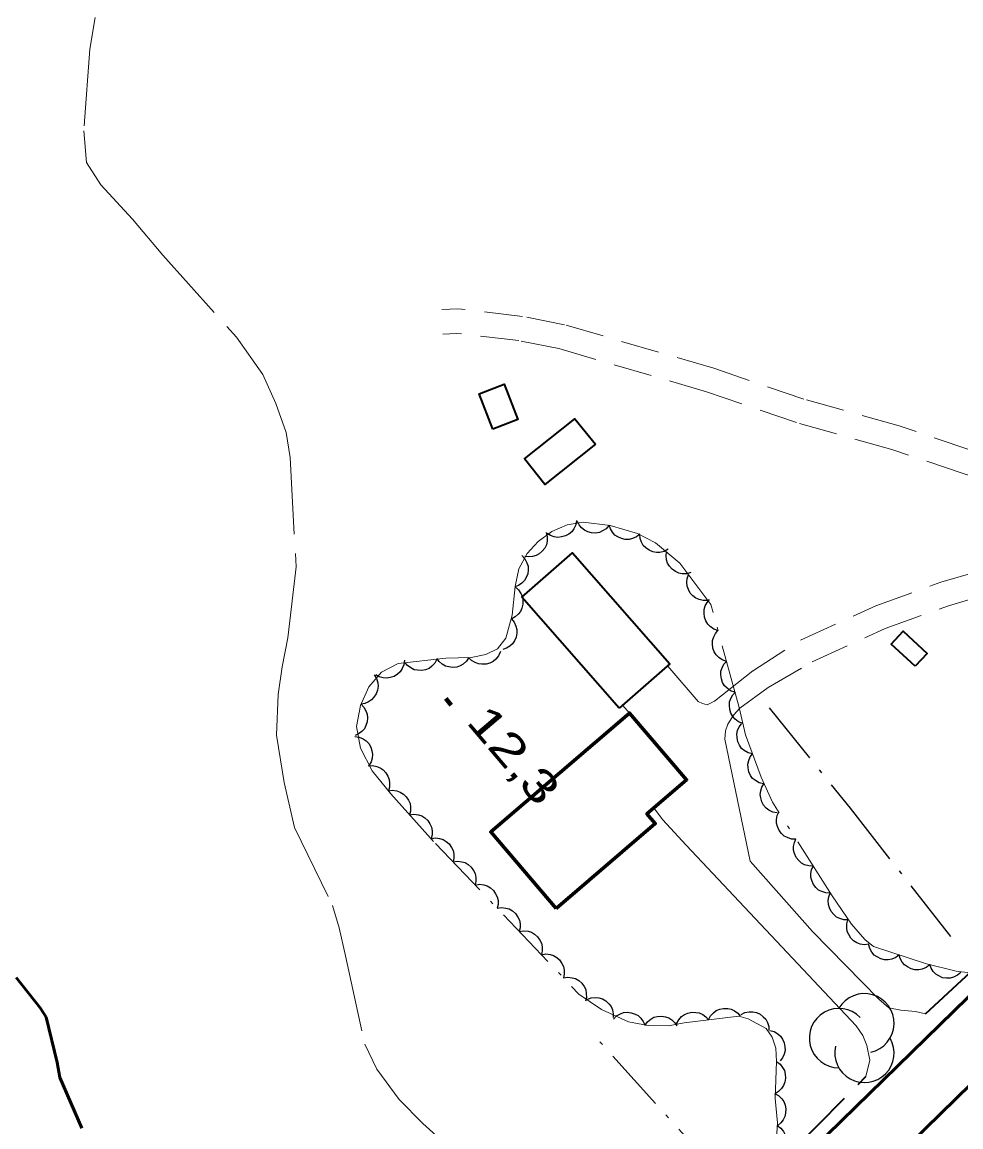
# Model space of a CAD drawing. Extents: x 386081 to 389416, y 5130568 to 5134082.
# Drawn here: x 387086.1 to 387174, y 5132079.6 to 5132183 of the extents above; entities that cross this region are included whole.
import ezdxf

# ---------------------------------------------------------------- set-up
doc = ezdxf.new("R2010")
doc.units = 0
doc.header["$LTSCALE"] = 1.2
for name, pattern in [('DOT_DASHED', [7.7, 5, -1.2, 0.3, -1.2]), ('LONG_DASHED', [7.5, 6, -1.5]), ('MEDIUM_DASHED', [4.5, 3, -1.5])]:
    doc.linetypes.add(name, pattern=pattern)
for name, color, linetype, lineweight in [('1', 7, 'Continuous', 53), ('19', 7, 'Continuous', 13), ('2', 7, 'Continuous', 13), ('21', 7, 'LONG_DASHED', 35), ('3', 7, 'Continuous', 140), ('31', 7, 'Continuous', 70), ('41', 7, 'DOT_DASHED', 25), ('44', 7, 'Continuous', 25)]:
    doc.layers.add(name, color=color, linetype=linetype, lineweight=lineweight)

msp = doc.modelspace()

# ---------------------------------------------------------------- linework, layer by layer
at = {"layer": '1', "linetype": 'LONG_DASHED'}
msp.add_lwpolyline([(387085.5, 5132093.55), (387087.75, 5132090.69), (387088.32, 5132089.82), (387089.35, 5132085.57), (387089.59, 5132084.18), (387091.67, 5132079.44)], dxfattribs=at)
at = {"layer": '19'}
msp.add_line((387142.96, 5132118.29), (387142.32, 5132119.01), dxfattribs=at)
at = {"layer": '19', "linetype": 'MEDIUM_DASHED'}
for points in [[(387209.48, 5132128.2), (387207.37, 5132128.87), (387203.75, 5132130.69), (387199.52, 5132133.4), (387195.36, 5132135.58), (387191.22, 5132137.3), (387187.74, 5132138.4), (387182.04, 5132140.71), (387174.91, 5132142.9), (387168.21, 5132145.18), (387159.28, 5132147.68), (387150.86, 5132150.57), (387136.88, 5132154.65), (387132.94, 5132155.43), (387126.88, 5132156.15), (387125.38, 5132156.08)], [(387154.47, 5132122.21), (387158.98, 5132125.13), (387166.02, 5132128.33), (387172.12, 5132130.54), (387177.06, 5132131.99), (387188.02, 5132136.04), (387181.26, 5132138.54), (387174.21, 5132140.71), (387167.53, 5132142.98), (387158.59, 5132145.48), (387150.16, 5132148.37), (387136.33, 5132152.42), (387132.58, 5132153.16), (387126.79, 5132153.84), (387125.48, 5132153.78)], [(387155.94, 5132120.7), (387160.07, 5132123.09), (387166.89, 5132126.2), (387172.83, 5132128.34), (387177.78, 5132129.8), (387188.83, 5132133.88), (387189.46, 5132134.19), (387189.9, 5132134.34), (387190.65, 5132134.44), (387191.33, 5132134.37), (387193.9, 5132133.45), (387198.23, 5132131.18), (387204.42, 5132126.51), (387204.98, 5132125.78), (387205.95, 5132124.13)]]:
    msp.add_lwpolyline(points, dxfattribs=at)
at = {"layer": '19'}
for points in [[(387146.53, 5132122.68), (387149.4, 5132119.38), (387149.78, 5132119.18), (387150.24, 5132119.07), (387150.91, 5132119.41), (387154.52, 5132122.25)], [(387170.67, 5132090.15), (387169.74, 5132090.36), (387168.38, 5132090.48), (387167.24, 5132090.71), (387166.31, 5132091.5), (387160.11, 5132097.84), (387154.27, 5132104.43), (387151.87, 5132115.86), (387151.94, 5132116.63), (387152.17, 5132117.25), (387152.69, 5132118.09), (387153.28, 5132118.76), (387155.94, 5132120.7)], [(387165.08, 5132084.26), (387165.45, 5132085.8), (387165.19, 5132087.18), (387164.82, 5132088.11), (387164.18, 5132089.01), (387148.26, 5132105.93), (387146.04, 5132108.33), (387145.24, 5132109.43)]]:
    msp.add_lwpolyline(points, dxfattribs=at)
at = {"layer": '2', "linetype": 'LONG_DASHED'}
msp.add_lwpolyline([(387092.91, 5132183.41), (387092.4, 5132180.45), (387091.86, 5132172.81), (387092.09, 5132169.85), (387093.45, 5132167.75), (387096.4, 5132164.52), (387099.24, 5132161.17), (387106.14, 5132153.47), (387108.6, 5132150), (387109.83, 5132147.28), (387110.81, 5132144.56), (387111.16, 5132142.22), (387111.73, 5132131.98), (387110.95, 5132125.33), (387110.43, 5132122.62), (387110.05, 5132120.04), (387109.9, 5132116.22), (387110.62, 5132111.78), (387111.59, 5132107.58), (387115.15, 5132100.28), (387115.75, 5132098.18), (387116.36, 5132095.58), (387118.17, 5132087.31), (387119.28, 5132084.96), (387121.37, 5132082.11), (387123.59, 5132079.87), (387125.81, 5132077.88)], dxfattribs=at)
at = {"layer": '21', "linetype": 'Continuous', "lineweight": 53}
for points in [[(387012.51, 5131910.8), (387021.08, 5131926.01), (387027.11, 5131935.62), (387032.84, 5131944.26), (387041.79, 5131956.43), (387052.62, 5131969.96), (387063.03, 5131981.26), (387078.48, 5131997.51), (387098.33, 5132017.4), (387121.9, 5132040.2), (387177.29, 5132094.24), (387231.65, 5132148.34), (387255.86, 5132172.16), (387275.84, 5132191.54), (387323.76, 5132237.29), (387346.1, 5132259.65), (387398.36, 5132310.48), (387454.62, 5132364.63)], [(387164.72, 5131800.51), (387132.8, 5131839.87), (387092.63, 5131890.18), (387081.09, 5131904.74), (387066.45, 5131922.63), (387054.56, 5131937.69), (387051.33, 5131941.01), (387048.28, 5131943.8), (387047.55, 5131945.3), (387046.77, 5131948.88), (387046.55, 5131951.09), (387046.66, 5131953.51), (387053.66, 5131962.18), (387060.66, 5131970.37), (387073.31, 5131984.05), (387083.84, 5131994.54), (387097.28, 5132007.63), (387119.07, 5132029.15), (387136.21, 5132045.69), (387190.72, 5132099), (387248.29, 5132155.99)]]:
    msp.add_lwpolyline(points, dxfattribs=at)
at = {"layer": '21'}
for points in [[(387170.67, 5132090.15), (387174.5, 5132093.65), (387198.02, 5132116.17), (387205.95, 5132124.13)], [(387090.92, 5132011.03), (387104.6, 5132024.53), (387129.07, 5132048.91), (387158.04, 5132077.13), (387165.08, 5132084.26)]]:
    msp.add_lwpolyline(points, dxfattribs=at)
at = {"layer": '3'}
msp.add_line((387125.75, 5132119.65), (387126.26, 5132119.04), dxfattribs=at)
at = {"layer": '31', "lineweight": 35}
for points in [[(387130.15, 5132144.87), (387128.87, 5132148.18), (387131.23, 5132149.09), (387132.51, 5132145.78)], [(387139.76, 5132143.46), (387135.04, 5132139.7), (387133.13, 5132142.09), (387137.85, 5132145.84)], [(387141.98, 5132118.75), (387132.87, 5132129.15), (387137.62, 5132133.3), (387146.73, 5132122.91)], [(387169.7, 5132122.67), (387167.45, 5132124.74), (387168.58, 5132125.96), (387170.83, 5132123.88)]]:
    msp.add_lwpolyline(points, close=True, dxfattribs=at)
at = {"layer": '31'}
msp.add_lwpolyline([(387136.09, 5132100), (387129.96, 5132107.17), (387142.96, 5132118.29), (387148.3, 5132112.05), (387144.58, 5132108.86), (387145.36, 5132107.94)], close=True, dxfattribs=at)
at = {"layer": '41'}
msp.add_line((387151.6, 5132074.88), (387139.49, 5132088.28), dxfattribs=at)
msp.add_lwpolyline([(387156.04, 5132118.77), (387163.61, 5132109.38), (387173.87, 5132096.29)], dxfattribs=at)
at = {"layer": '44', "linetype": 'DOT_DASHED', "lineweight": 13}
for points in [[(387170.77, 5132094.82), (387165.81, 5132096.44), (387164.99, 5132097.09), (387163.74, 5132098.53), (387161.94, 5132101.17), (387156.34, 5132109.94), (387155.28, 5132112.28), (387153.82, 5132116.24), (387153.22, 5132118.8), (387150.58, 5132128.46), (387147.66, 5132132.33), (387145.39, 5132134.24), (387143.71, 5132135.11), (387141.13, 5132135.86), (387138.62, 5132136.16), (387137.11, 5132135.92), (387135.69, 5132135.3), (387134.41, 5132134.37), (387133.37, 5132133.22), (387132.6, 5132131.79), (387132.24, 5132130.13), (387131.98, 5132127.45), (387131.38, 5132125.3), (387130.6, 5132124.3), (387129.5, 5132123.78), (387128.12, 5132123.51), (387125.76, 5132123.43), (387121.3, 5132122.94), (387119.73, 5132122.13), (387118.54, 5132120.76), (387117.75, 5132119.01), (387117.4, 5132117.05), (387117.77, 5132115.01), (387118.84, 5132112.88), (387120.59, 5132110.74), (387124.79, 5132106.08), (387138.22, 5132091.98), (387140.33, 5132090.54), (387142.86, 5132089.38), (387144.71, 5132089.04), (387146.61, 5132089.01), (387148.09, 5132089.3), (387153.18, 5132089.91), (387154.08, 5132089.68), (387155.75, 5132088.75), (387156.31, 5132087.95), (387156.66, 5132086.92), (387156.72, 5132085.66), (387156.6, 5132082.2), (387156.82, 5132079.94), (387156.7, 5132078)], [(387175.61, 5132093.88), (387173.55, 5132094.13), (387170.77, 5132094.82)]]:
    msp.add_lwpolyline(points, dxfattribs=at)
at = {"layer": '44'}
for points in [[(387138, 5132136.31), (387137.92, 5132135.9), (387137.74, 5132135.54), (387137.55, 5132135.27), (387137.27, 5132135.05), (387136.95, 5132134.87), (387136.58, 5132134.78), (387136.25, 5132134.73), (387135.91, 5132134.79), (387135.56, 5132134.92), (387135.25, 5132135.11)], [(387141.05, 5132135.87), (387140.77, 5132135.55), (387140.43, 5132135.34), (387140.13, 5132135.2), (387139.78, 5132135.15), (387139.41, 5132135.16), (387139.04, 5132135.27), (387138.74, 5132135.4), (387138.47, 5132135.62), (387138.23, 5132135.91), (387138.07, 5132136.23)], [(387143.93, 5132135.05), (387143.61, 5132134.78), (387143.23, 5132134.62), (387142.91, 5132134.54), (387142.56, 5132134.54), (387142.2, 5132134.62), (387141.86, 5132134.78), (387141.58, 5132134.95), (387141.35, 5132135.22), (387141.16, 5132135.54), (387141.05, 5132135.88)], [(387135.15, 5132135.19), (387135.25, 5132134.78), (387135.23, 5132134.38), (387135.17, 5132134.05), (387135.01, 5132133.74), (387134.78, 5132133.45), (387134.48, 5132133.21), (387134.21, 5132133.03), (387133.86, 5132132.95), (387133.49, 5132132.91), (387133.14, 5132132.96)], [(387146.58, 5132133.63), (387146.21, 5132133.43), (387145.81, 5132133.34), (387145.48, 5132133.32), (387145.14, 5132133.4), (387144.8, 5132133.54), (387144.49, 5132133.77), (387144.25, 5132133.99), (387144.08, 5132134.3), (387143.96, 5132134.65), (387143.91, 5132135)], [(387132.87, 5132133.04), (387133.16, 5132132.74), (387133.34, 5132132.37), (387133.45, 5132132.06), (387133.47, 5132131.71), (387133.42, 5132131.34), (387133.28, 5132130.99), (387133.13, 5132130.7), (387132.87, 5132130.45), (387132.57, 5132130.24), (387132.24, 5132130.11)], [(387148.71, 5132131.45), (387148.31, 5132131.33), (387147.9, 5132131.34), (387147.57, 5132131.39), (387147.26, 5132131.54), (387146.95, 5132131.75), (387146.71, 5132132.05), (387146.52, 5132132.32), (387146.42, 5132132.65), (387146.38, 5132133.02), (387146.41, 5132133.38)], [(387150.29, 5132128.84), (387149.87, 5132128.82), (387149.48, 5132128.92), (387149.17, 5132129.04), (387148.9, 5132129.26), (387148.65, 5132129.53), (387148.47, 5132129.87), (387148.35, 5132130.18), (387148.33, 5132130.53), (387148.37, 5132130.9), (387148.49, 5132131.24)], [(387132.24, 5132130.11), (387132.56, 5132129.84), (387132.78, 5132129.5), (387132.93, 5132129.2), (387132.98, 5132128.86), (387132.98, 5132128.49), (387132.88, 5132128.12), (387132.76, 5132127.81), (387132.54, 5132127.54), (387132.26, 5132127.29), (387131.95, 5132127.12)], [(387151.24, 5132126.03), (387150.85, 5132126.16), (387150.52, 5132126.4), (387150.28, 5132126.63), (387150.1, 5132126.93), (387149.97, 5132127.28), (387149.94, 5132127.66), (387149.94, 5132127.98), (387150.05, 5132128.32), (387150.22, 5132128.65), (387150.45, 5132128.92)], [(387131.89, 5132127.13), (387132.16, 5132126.81), (387132.32, 5132126.44), (387132.41, 5132126.12), (387132.41, 5132125.77), (387132.34, 5132125.41), (387132.18, 5132125.06), (387132.01, 5132124.78), (387131.74, 5132124.55), (387131.43, 5132124.36), (387131.08, 5132124.24)], [(387152.04, 5132123.13), (387151.64, 5132123.27), (387151.31, 5132123.51), (387151.07, 5132123.73), (387150.89, 5132124.04), (387150.77, 5132124.38), (387150.73, 5132124.76), (387150.73, 5132125.09), (387150.84, 5132125.42), (387151.01, 5132125.75), (387151.24, 5132126.03)], [(387121.87, 5132123.23), (387121.82, 5132122.82), (387121.66, 5132122.45), (387121.49, 5132122.16), (387121.22, 5132121.93), (387120.91, 5132121.73), (387120.55, 5132121.62), (387120.23, 5132121.55), (387119.88, 5132121.59), (387119.52, 5132121.69), (387119.2, 5132121.86)], [(387124.92, 5132123.34), (387124.72, 5132122.97), (387124.44, 5132122.68), (387124.18, 5132122.48), (387123.85, 5132122.35), (387123.49, 5132122.28), (387123.1, 5132122.3), (387122.78, 5132122.35), (387122.47, 5132122.52), (387122.17, 5132122.74), (387121.94, 5132123.01)], [(387127.91, 5132123.5), (387127.69, 5132123.15), (387127.38, 5132122.88), (387127.11, 5132122.7), (387126.77, 5132122.6), (387126.4, 5132122.56), (387126.02, 5132122.61), (387125.71, 5132122.68), (387125.41, 5132122.87), (387125.13, 5132123.11), (387124.91, 5132123.4)], [(387130.86, 5132124.05), (387130.7, 5132123.66), (387130.44, 5132123.35), (387130.19, 5132123.13), (387129.88, 5132122.97), (387129.52, 5132122.87), (387129.14, 5132122.86), (387128.81, 5132122.89), (387128.49, 5132123.02), (387128.17, 5132123.22), (387127.92, 5132123.47)], [(387152.83, 5132120.24), (387152.43, 5132120.37), (387152.1, 5132120.61), (387151.86, 5132120.84), (387151.68, 5132121.14), (387151.56, 5132121.49), (387151.52, 5132121.87), (387151.52, 5132122.2), (387151.63, 5132122.53), (387151.8, 5132122.86), (387152.04, 5132123.13)], [(387119.04, 5132121.87), (387119.26, 5132121.52), (387119.37, 5132121.13), (387119.41, 5132120.8), (387119.35, 5132120.45), (387119.23, 5132120.1), (387119.01, 5132119.78), (387118.8, 5132119.53), (387118.5, 5132119.35), (387118.16, 5132119.2), (387117.81, 5132119.14)], [(387153.56, 5132117.33), (387153.17, 5132117.48), (387152.85, 5132117.73), (387152.62, 5132117.97), (387152.46, 5132118.28), (387152.34, 5132118.63), (387152.32, 5132119.01), (387152.33, 5132119.34), (387152.45, 5132119.67), (387152.64, 5132119.99), (387152.88, 5132120.25)], [(387117.78, 5132119.15), (387118.07, 5132118.86), (387118.27, 5132118.5), (387118.39, 5132118.2), (387118.42, 5132117.84), (387118.39, 5132117.48), (387118.26, 5132117.12), (387118.12, 5132116.82), (387117.87, 5132116.57), (387117.58, 5132116.34), (387117.25, 5132116.2)], [(387154.47, 5132114.48), (387154.06, 5132114.58), (387153.71, 5132114.79), (387153.46, 5132114.99), (387153.25, 5132115.28), (387153.1, 5132115.61), (387153.03, 5132115.99), (387153, 5132116.31), (387153.08, 5132116.66), (387153.22, 5132117), (387153.43, 5132117.29)], [(387117.23, 5132116.09), (387117.64, 5132116.03), (387118.01, 5132115.87), (387118.29, 5132115.69), (387118.53, 5132115.43), (387118.72, 5132115.11), (387118.83, 5132114.75), (387118.9, 5132114.43), (387118.85, 5132114.08), (387118.75, 5132113.72), (387118.57, 5132113.41)], [(387155.51, 5132111.66), (387155.1, 5132111.76), (387154.75, 5132111.97), (387154.49, 5132112.18), (387154.29, 5132112.46), (387154.13, 5132112.8), (387154.06, 5132113.17), (387154.04, 5132113.5), (387154.12, 5132113.84), (387154.26, 5132114.18), (387154.47, 5132114.48)], [(387118.47, 5132113.34), (387118.88, 5132113.37), (387119.28, 5132113.29), (387119.59, 5132113.18), (387119.88, 5132112.98), (387120.13, 5132112.71), (387120.32, 5132112.38), (387120.46, 5132112.08), (387120.49, 5132111.73), (387120.47, 5132111.36), (387120.37, 5132111.01)], [(387120.35, 5132111), (387120.77, 5132111.06), (387121.17, 5132111), (387121.48, 5132110.9), (387121.78, 5132110.71), (387122.05, 5132110.46), (387122.25, 5132110.14), (387122.4, 5132109.84), (387122.45, 5132109.5), (387122.45, 5132109.12), (387122.36, 5132108.78)], [(387156.79, 5132108.95), (387156.38, 5132109.02), (387156.01, 5132109.2), (387155.74, 5132109.39), (387155.52, 5132109.66), (387155.34, 5132109.98), (387155.24, 5132110.35), (387155.19, 5132110.67), (387155.25, 5132111.02), (387155.36, 5132111.37), (387155.55, 5132111.68)], [(387122.36, 5132108.78), (387122.77, 5132108.83), (387123.18, 5132108.77), (387123.49, 5132108.68), (387123.79, 5132108.48), (387124.06, 5132108.23), (387124.26, 5132107.91), (387124.41, 5132107.62), (387124.46, 5132107.27), (387124.46, 5132106.9), (387124.37, 5132106.55)], [(387158.54, 5132106.49), (387158.12, 5132106.5), (387157.74, 5132106.63), (387157.44, 5132106.78), (387157.18, 5132107.02), (387156.96, 5132107.31), (387156.81, 5132107.66), (387156.71, 5132107.97), (387156.72, 5132108.33), (387156.78, 5132108.69), (387156.93, 5132109.02)], [(387124.36, 5132106.53), (387124.77, 5132106.6), (387125.17, 5132106.55), (387125.49, 5132106.47), (387125.79, 5132106.28), (387126.07, 5132106.04), (387126.28, 5132105.72), (387126.43, 5132105.43), (387126.5, 5132105.09), (387126.5, 5132104.71), (387126.43, 5132104.36)], [(387160.16, 5132103.97), (387159.74, 5132103.98), (387159.35, 5132104.1), (387159.05, 5132104.25), (387158.8, 5132104.49), (387158.57, 5132104.78), (387158.42, 5132105.13), (387158.33, 5132105.45), (387158.33, 5132105.8), (387158.4, 5132106.16), (387158.54, 5132106.49)], [(387126.43, 5132104.36), (387126.84, 5132104.43), (387127.24, 5132104.38), (387127.56, 5132104.29), (387127.86, 5132104.11), (387128.14, 5132103.87), (387128.35, 5132103.55), (387128.5, 5132103.26), (387128.57, 5132102.91), (387128.57, 5132102.54), (387128.49, 5132102.19)], [(387161.77, 5132101.44), (387161.35, 5132101.45), (387160.97, 5132101.58), (387160.67, 5132101.72), (387160.41, 5132101.96), (387160.19, 5132102.25), (387160.04, 5132102.61), (387159.94, 5132102.92), (387159.95, 5132103.27), (387160.01, 5132103.63), (387160.16, 5132103.97)], [(387128.49, 5132102.19), (387128.91, 5132102.26), (387129.31, 5132102.21), (387129.63, 5132102.12), (387129.93, 5132101.94), (387130.21, 5132101.69), (387130.42, 5132101.38), (387130.57, 5132101.09), (387130.64, 5132100.74), (387130.64, 5132100.37), (387130.56, 5132100.02)], [(387163.45, 5132098.95), (387163.03, 5132098.95), (387162.64, 5132099.07), (387162.34, 5132099.2), (387162.08, 5132099.43), (387161.84, 5132099.72), (387161.68, 5132100.07), (387161.58, 5132100.38), (387161.57, 5132100.73), (387161.63, 5132101.1), (387161.76, 5132101.43)], [(387130.56, 5132100.02), (387130.98, 5132100.09), (387131.38, 5132100.03), (387131.7, 5132099.95), (387132, 5132099.77), (387132.27, 5132099.52), (387132.49, 5132099.2), (387132.64, 5132098.91), (387132.7, 5132098.57), (387132.71, 5132098.2), (387132.63, 5132097.85)], [(387165.37, 5132096.65), (387164.96, 5132096.6), (387164.56, 5132096.67), (387164.24, 5132096.77), (387163.95, 5132096.97), (387163.68, 5132097.23), (387163.49, 5132097.55), (387163.35, 5132097.85), (387163.3, 5132098.2), (387163.31, 5132098.57), (387163.4, 5132098.92)], [(387132.63, 5132097.85), (387133.04, 5132097.91), (387133.45, 5132097.86), (387133.77, 5132097.78), (387134.07, 5132097.59), (387134.34, 5132097.35), (387134.56, 5132097.03), (387134.71, 5132096.74), (387134.77, 5132096.4), (387134.78, 5132096.03), (387134.7, 5132095.67)], [(387168.22, 5132095.65), (387167.89, 5132095.4), (387167.51, 5132095.25), (387167.19, 5132095.18), (387166.84, 5132095.2), (387166.48, 5132095.28), (387166.14, 5132095.46), (387165.87, 5132095.64), (387165.65, 5132095.91), (387165.47, 5132096.24), (387165.37, 5132096.58)], [(387134.7, 5132095.67), (387135.11, 5132095.74), (387135.52, 5132095.69), (387135.84, 5132095.6), (387136.14, 5132095.42), (387136.41, 5132095.18), (387136.63, 5132094.86), (387136.78, 5132094.57), (387136.84, 5132094.22), (387136.85, 5132093.85), (387136.77, 5132093.5)], [(387171.07, 5132094.72), (387170.74, 5132094.47), (387170.36, 5132094.32), (387170.04, 5132094.24), (387169.69, 5132094.26), (387169.33, 5132094.35), (387168.99, 5132094.53), (387168.72, 5132094.71), (387168.5, 5132094.98), (387168.32, 5132095.31), (387168.22, 5132095.65)], [(387173.99, 5132094.02), (387173.68, 5132093.74), (387173.31, 5132093.57), (387173, 5132093.47), (387172.64, 5132093.46), (387172.28, 5132093.52), (387171.93, 5132093.68), (387171.64, 5132093.84), (387171.41, 5132094.1), (387171.2, 5132094.41), (387171.08, 5132094.74)], [(387136.77, 5132093.5), (387137.18, 5132093.57), (387137.59, 5132093.52), (387137.91, 5132093.43), (387138.21, 5132093.25), (387138.48, 5132093), (387138.7, 5132092.69), (387138.85, 5132092.4), (387138.91, 5132092.05), (387138.92, 5132091.68), (387138.84, 5132091.33)], [(387138.96, 5132091.47), (387139.35, 5132091.63), (387139.76, 5132091.66), (387140.09, 5132091.64), (387140.42, 5132091.53), (387140.74, 5132091.35), (387141.02, 5132091.08), (387141.23, 5132090.83), (387141.36, 5132090.5), (387141.44, 5132090.14), (387141.44, 5132089.78)], [(387141.45, 5132089.64), (387141.74, 5132089.94), (387142.1, 5132090.13), (387142.4, 5132090.25), (387142.75, 5132090.28), (387143.12, 5132090.24), (387143.48, 5132090.11), (387143.77, 5132089.97), (387144.03, 5132089.72), (387144.25, 5132089.43), (387144.4, 5132089.1)], [(387147.37, 5132089.21), (387147.56, 5132089.58), (387147.84, 5132089.88), (387148.1, 5132090.08), (387148.43, 5132090.21), (387148.79, 5132090.29), (387149.17, 5132090.27), (387149.49, 5132090.22), (387149.81, 5132090.06), (387150.11, 5132089.84), (387150.35, 5132089.57)], [(387150.35, 5132089.57), (387150.54, 5132089.94), (387150.82, 5132090.23), (387151.08, 5132090.44), (387151.41, 5132090.57), (387151.77, 5132090.64), (387152.15, 5132090.62), (387152.47, 5132090.57), (387152.79, 5132090.42), (387153.09, 5132090.2), (387153.32, 5132089.93)], [(387153.4, 5132090.06), (387153.77, 5132090.25), (387154.17, 5132090.32), (387154.5, 5132090.33), (387154.84, 5132090.25), (387155.18, 5132090.09), (387155.48, 5132089.85), (387155.71, 5132089.63), (387155.87, 5132089.31), (387155.99, 5132088.96), (387156.02, 5132088.6)], [(387144.39, 5132089.05), (387144.63, 5132089.39), (387144.95, 5132089.64), (387145.23, 5132089.81), (387145.58, 5132089.89), (387145.94, 5132089.92), (387146.32, 5132089.85), (387146.63, 5132089.75), (387146.92, 5132089.56), (387147.19, 5132089.3), (387147.39, 5132089)], [(387156.09, 5132088.59), (387156.5, 5132088.48), (387156.84, 5132088.26), (387157.09, 5132088.05), (387157.29, 5132087.75), (387157.44, 5132087.42), (387157.5, 5132087.04), (387157.52, 5132086.71), (387157.43, 5132086.37), (387157.28, 5132086.03), (387157.06, 5132085.74)], [(387156.72, 5132085.68), (387157.06, 5132085.43), (387157.3, 5132085.11), (387157.47, 5132084.82), (387157.54, 5132084.48), (387157.56, 5132084.11), (387157.49, 5132083.73), (387157.39, 5132083.42), (387157.18, 5132083.14), (387156.92, 5132082.87), (387156.62, 5132082.68)], [(387156.55, 5132082.68), (387156.92, 5132082.48), (387157.21, 5132082.19), (387157.4, 5132081.93), (387157.53, 5132081.6), (387157.59, 5132081.23), (387157.57, 5132080.85), (387157.51, 5132080.53), (387157.35, 5132080.22), (387157.12, 5132079.92), (387156.84, 5132079.69)], [(387156.8, 5132079.69), (387157.14, 5132079.44), (387157.37, 5132079.11), (387157.53, 5132078.82), (387157.59, 5132078.47), (387157.6, 5132078.1), (387157.52, 5132077.73), (387157.41, 5132077.42), (387157.2, 5132077.14), (387156.93, 5132076.88), (387156.62, 5132076.7)]]:
    msp.add_lwpolyline(points, dxfattribs=at)
for centre, start, end in [((387164.96, 5132089.252), 282.26917, 149.72626), ((387164.96, 5132089.252), 282.26917, 149.72626), ((387162.571, 5132087.863), 44.11537, 269.80396), ((387162.571, 5132087.863), 44.11537, 269.80396), ((387164.96, 5132086.474), 166.93686, 29.62122), ((387164.96, 5132086.474), 166.93686, 29.62122)]:
    msp.add_arc(centre, 2.777, start, end, dxfattribs=at)

# ---------------------------------------------------------------- texts
at = {"layer": '3', "width": 1.35}
msp.add_text('12,3   ', height=3, rotation=310.294, dxfattribs=at).set_placement((387127.58, 5132117.43))

doc.saveas('drawing.dxf')
